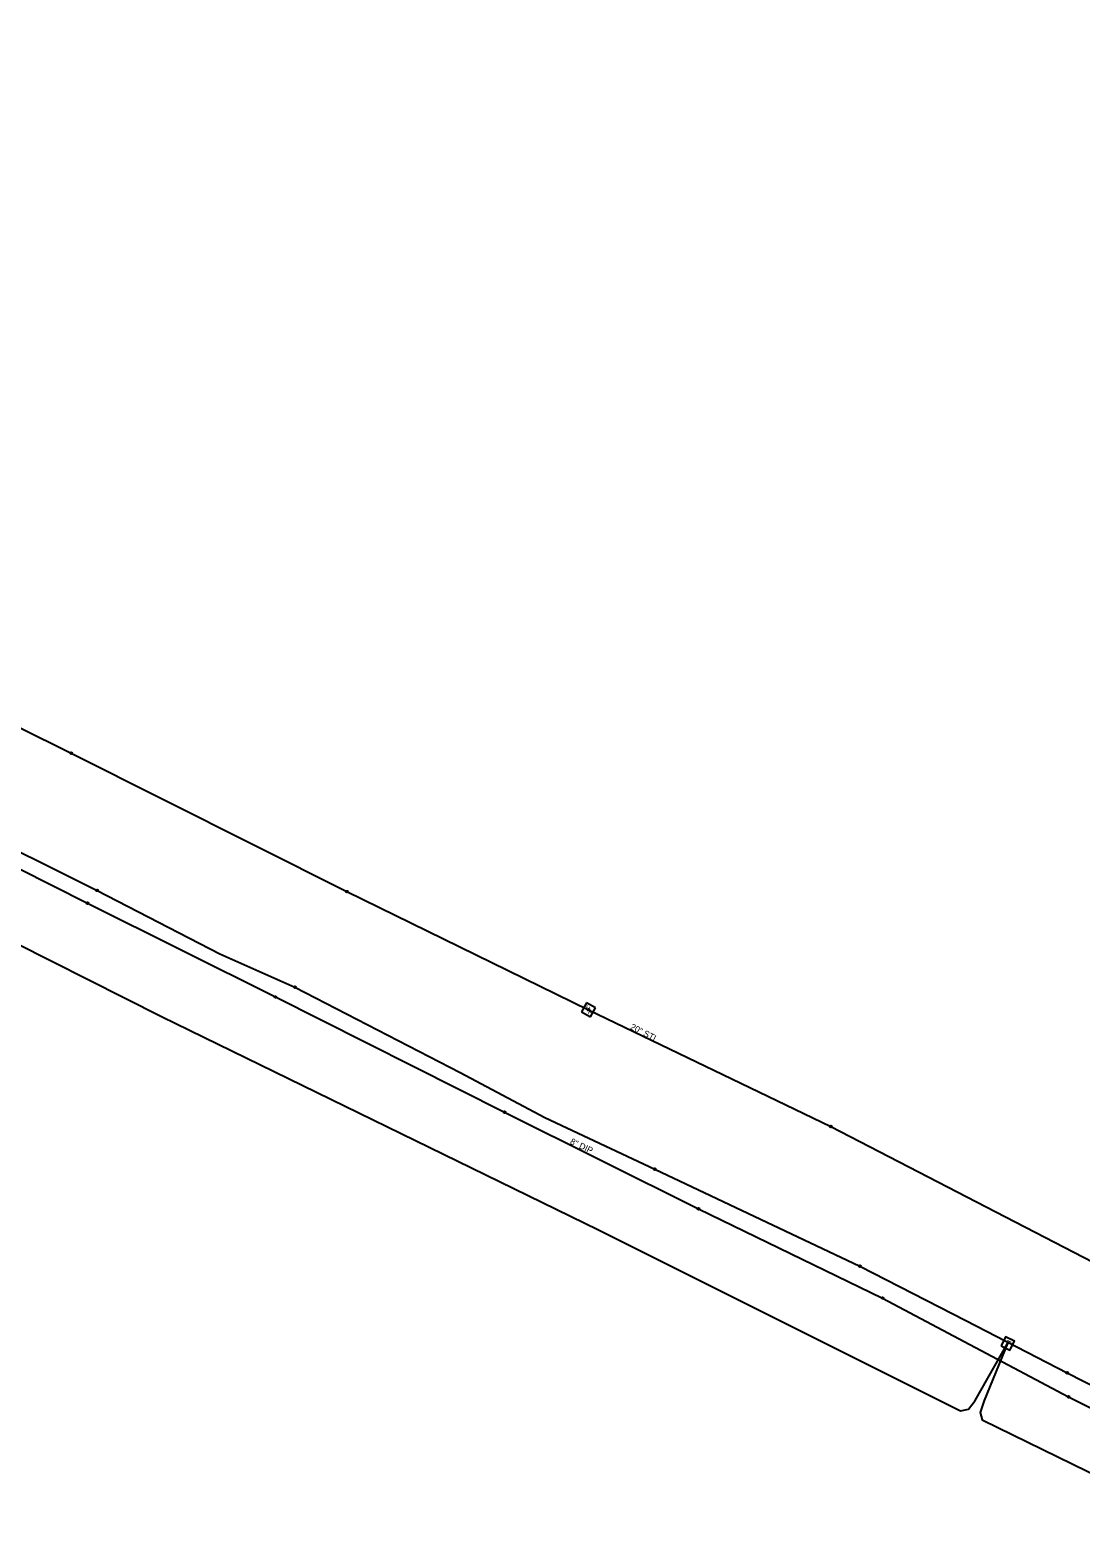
# Model space of a CAD drawing. Extents: x 2244485 to 2250986, y 199568 to 203007.
# Drawn here: x 2247155 to 2247742, y 201272 to 202115 of the extents above; entities that cross this region are included whole.
import ezdxf

# ---------------------------------------------------------------- set-up
doc = ezdxf.new("R2010")
doc.units = 0
for name, color, linetype in [('Default', 7, 'Continuous'), ('Exist Utilities Gas Meter CELL', 7, 'Continuous'), ('Exist Utilities Gas UG Line SUE LOS B', 7, 'Continuous'), ('Exist Utilities Gas UG Line SUE LOS B Text', 7, 'Continuous'), ('Exist Utilities Sanitary Sewer Forced Main SUE LOS B', 7, 'Continuous'), ('Exist Utilities Sanitary Sewer Forced Main SUE LOS B Text', 7, 'Continuous'), ('Exist Utilities Telephone Pedestal CELL', 7, 'Continuous'), ('Exist Utilities Telephone UG Cable SUE LOS C', 7, 'Continuous'), ('Exist Utilities Telephone UG FO SUE LOS B', 7, 'Continuous')]:
    doc.layers.add(name, color=color, linetype=linetype)

# ---------------------------------------------------------------- blocks, each defined once
blk = doc.blocks.new('SurveyPointCell')
at = {"layer": 'Default'}
for p, q in [((-0.5, 0), (0.5, 0)), ((0, -0.5), (0, 0.5))]:
    blk.add_line(p, q, dxfattribs=at)
blk.add_circle((0, 0), 0.5, dxfattribs=at)

msp = doc.modelspace()

# ---------------------------------------------------------------- linework, layer by layer
at = {"layer": 'Exist Utilities Gas Meter CELL'}
for p, q in [((2247465.69, 201571.09), (2247462.92, 201566.07)), ((2247462.92, 201566.07), (2247467.93, 201563.31)), ((2247470.7, 201568.32), (2247465.69, 201571.09)), ((2247466.81, 201567.2), (2247466.81, 201567.2)), ((2247467.93, 201563.31), (2247470.7, 201568.32))]:
    msp.add_line(p, q, dxfattribs=at)
at = {"layer": 'Exist Utilities Gas UG Line SUE LOS B'}
msp.add_lwpolyline([(2244658.96, 202958.49), (2244721.96, 202928.3), (2244863.47, 202856.19), (2244912.51, 202831.57), (2245070.07, 202752.33), (2245256.14, 202659.91), (2245331.4, 202622.29), (2245514.38, 202531.76), (2245606.53, 202488.05), (2245652.12, 202465.42), (2245827.69, 202375.08), (2246001.01, 202291.84), (2246162.3, 202211.17), (2246329.12, 202125.74), (2246513.99, 202036.93), (2246642.7, 201974.75), (2246734.96, 201930.33), (2246858.92, 201868.26), (2246999.42, 201799.12), (2247177.53, 201710.71), (2247331.7, 201633.3), (2247466.92, 201567.22), (2247602.4, 201501.88), (2247749.1, 201426.01)], dxfattribs=at)
at = {"layer": 'Exist Utilities Sanitary Sewer Forced Main SUE LOS B'}
msp.add_lwpolyline([(2245613.42, 202432.81), (2245612.33, 202430.62), (2245623.88, 202401.25), (2245742.14, 202343.1), (2245917.37, 202257.79), (2246026.41, 202202.34), (2246210.46, 202111.93), (2246345.24, 202046.28), (2246501.59, 201967.74), (2246585.87, 201926.12), (2246766.44, 201836.2), (2246874.3, 201784.12), (2246993.56, 201724.08), (2247186.6, 201626.85), (2247291.7, 201574.36), (2247419.93, 201509.91), (2247528.38, 201455.85), (2247631.36, 201405.97), (2247735.41, 201350.67), (2247801.59, 201317.51)], dxfattribs=at)
at = {"layer": 'Exist Utilities Telephone Pedestal CELL'}
msp.add_line((2247701.3, 201380.55), (2247701.3, 201380.55), dxfattribs=at)
msp.add_lwpolyline([(2247697.61, 201379.23), (2247702.61, 201376.74), (2247705.11, 201381.75), (2247700.1, 201384.24), (2247697.61, 201379.23)], dxfattribs=at)
at = {"layer": 'Exist Utilities Telephone UG Cable SUE LOS C'}
msp.add_lwpolyline([(2246473.42, 201940.75), (2246700.68, 201828.04), (2246918.29, 201719.79), (2246967.49, 201693.76), (2246972.21, 201694.04), (2246978.56, 201699.41), (2247000.3, 201730.52), (2246984.26, 201697.47), (2246981.09, 201689.73), (2246982.67, 201686.82), (2247023.03, 201666.72), (2247227.98, 201563.38), (2247472.41, 201444.11), (2247675.02, 201342.94), (2247679.49, 201343.77), (2247683.14, 201348.6), (2247701.3, 201380.55), (2247688.18, 201348.67), (2247685.95, 201341.92), (2247686.97, 201337.82), (2247821.99, 201271.82)], dxfattribs=at)
at = {"layer": 'Exist Utilities Telephone UG FO SUE LOS B'}
msp.add_lwpolyline([(2246544.1, 201955.85), (2246738.78, 201858.63), (2246806.46, 201826.48), (2246897.21, 201781.07), (2247041.24, 201709.01), (2247192.04, 201633.96), (2247260.63, 201598.54), (2247302.66, 201579.85), (2247395.02, 201532.05), (2247442.43, 201506.85), (2247503.92, 201478.03), (2247618.67, 201423.77), (2247677.96, 201393.41), (2247734.6, 201364.13), (2247798.15, 201331.66)], dxfattribs=at)

# ---------------------------------------------------------------- block references
at = {"layer": 'Default'}
for p in [(2247177.53, 201710.71), (2247192.04, 201633.96), (2247331.7, 201633.3), (2247186.6, 201626.85), (2247291.7, 201574.36), (2247302.66, 201579.85), (2247466.92, 201567.22), (2247419.93, 201509.91), (2247602.4, 201501.88), (2247503.92, 201478.03), (2247528.38, 201455.85), (2247618.67, 201423.77), (2247631.36, 201405.97), (2247734.6, 201364.13), (2247735.41, 201350.67)]:
    msp.add_blockref('SurveyPointCell', p, dxfattribs=at)

# ---------------------------------------------------------------- texts
at = {"layer": 'Exist Utilities Gas Meter CELL'}
for p in [(2247464.7, 201567.69), (2247466.24, 201565.16)]:
    msp.add_text('H', height=2.5, rotation=331.07712, dxfattribs=at).set_placement(p)
at = {"layer": 'Exist Utilities Gas UG Line SUE LOS B Text'}
msp.add_text('20" STL', height=3.5, rotation=333.09153, dxfattribs=at).set_placement((2247489.89, 201556.52))
at = {"layer": 'Exist Utilities Sanitary Sewer Forced Main SUE LOS B Text'}
msp.add_text('8" DIP', height=3.5, rotation=334.4319, dxfattribs=at).set_placement((2247456.21, 201492.35))
at = {"layer": 'Exist Utilities Telephone Pedestal CELL'}
msp.add_text('T', height=3.42, rotation=333.54169, dxfattribs=at).set_placement((2247699.53, 201379.52))

doc.saveas('drawing.dxf')
